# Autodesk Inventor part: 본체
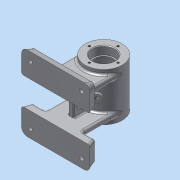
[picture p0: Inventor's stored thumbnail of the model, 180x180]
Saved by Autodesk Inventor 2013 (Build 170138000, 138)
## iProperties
Created: 2016-07
Part Number: 본체
Material: 알루미늄 6061
Document SubType Name: Modeling
Designer: dgall
Density: 1 g/cm^3
Author: dgall
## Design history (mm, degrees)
sketch "스케치1"
  geometry: C1 r 27 at (0, 0); 1 further point
  constraints: 1 centre point, 1 coincident
  dimensions: "d0" = 54 diameter of C1
extrude "돌출1" new body sketch "스케치1" distance "d2" = 70; taper "d3" = 0 deg
node "작업 평면1"
sketch "스케치2"
  geometry: L1 (27, 70)-(-27, 70) reference; L2 (-27, 0)-(27, 0) reference; L3 (50, 90)-(-50, 90); L4 (-50, 90)-(-50, -20); L5 (-50, -20)-(50, -20); L6 (50, -20)-(50, 90); L7 (27, 0)-(27, 70) reference; L8 (-27, 0)-(-27, 70) reference; 5 further points
  constraints: 8 end point, 4 midpoint, 2 parallel, 1 horizontal, 1 horizontal alignment, 1 perpendicular, 1 vertical alignment
  dimensions: "d5" = 100 distance between parallel lines of L4 L6; "d7" = 110 distance between parallel lines of L3 L5
extrude "돌출2" join sketch "스케치2" distance "d8" = 12; taper "d9" = -20 deg
sketch "스케치3"
  geometry: L1 (-70, 55)-(-58, 55); L2 (-58, 55)-(-58, 15); L3 (-58, 15)-(-70, 15); L4 (-70, 15)-(-70, 55); L5 (-58, -15.632)-(-58, 85.632) reference; L6 (-70, 90)-(-70, -20) reference; 6 further points
  constraints: 8 end point, 5 midpoint, 3 coincident, 2 parallel, 1 horizontal, 1 perpendicular
  dimensions: "d10" = 40 distance of L3.end L1.start
extrude "돌출3" cut sketch "스케치3" stored distance "d12" = 12; taper "d13" = 0 deg
sketch "스케치4"
  geometry: L1 (4.368, 12)-(95.632, 12) reference; L2 (23, 70)-(23, 12); L3 (77, 12)-(77, 70); A1 r 27 centre (50, 70) between (23, 70) and (77, 70) reference; 1 further point
  constraints: 4 end point, 2 perpendicular, 2 point on circle, 2 point on line, 1 parallel
  dimensions: "d14" = 54 distance between parallel lines of L3 L2
extrude "돌출4" join sketch "스케치4" distance "d15" = 8; taper "d16" = 0 deg
sketch "스케치5"
  geometry: L1 (4.368, 12)-(95.632, 12) reference; L2 (23, 70)-(23, 12); L3 (77, 12)-(77, 70); A1 r 27 centre (50, 70) between (23, 70) and (77, 70) reference; 1 further point
  constraints: 4 end point, 2 parallel, 2 point on circle, 2 point on line, 1 perpendicular
  dimensions: "d17" = 54 distance between parallel lines of L3 L2
extrude "돌출5" join sketch "스케치5" distance "d18" = 8; taper "d19" = 0 deg
sketch "스케치6"
  geometry: L1 (0, 55)-(-58, 55) reference; L2 (-58, 15)-(0, 15) reference; L3 (-48, 55)-(-22, 55); L4 (-22, 55)-(-22, 15); L5 (-22, 15)-(-48, 15); L6 (-48, 15)-(-48, 55); L7 (-34.5, 43)-(-34.5, 27); L8 (-41.5, 27)-(-41.5, 43); L9 (-70, 15)-(-70, -20) reference; L10 (-27, 0)-(-27, 70) reference; A1 r 3.5 centre (-38, 27) between (-41.5, 27) and (-34.5, 27); A2 r 3.5 centre (-38, 43) between (-34.5, 43) and (-41.5, 43); 3 further points
  constraints: 12 end point, 4 parallel, 4 point on circle, 4 tangent, 2 centre point, 2 midpoint, 2 point on line, 1 horizontal, 1 horizontal alignment, 1 perpendicular
  dimensions: "d20" = 3.5 radius of A1; "d22" = 32 distance from line of L9 A1.centre; "d23" = 23 dimension on A2 A1; "d24" = 21 distance between parallel lines of L6 L10; "d25" = 5 distance between parallel lines of L10 L4
extrude "돌출6" join sketch "스케치6" stored distance "d26" = 8; taper "d27" = 0 deg
node "작업 평면2"
sketch "스케치7"
  geometry: L1 (-27, 0)-(-27, 70) reference; L2 (27, 0)-(27, 70) reference; L3 (27, 70)-(-27, 70) reference; L4 (-27, 0)-(27, 0) reference; C1 r 5 at (0, 22); 2 further points
  constraints: 1 centre point, 1 midpoint, 1 vertical alignment
  dimensions: "d28" = 22 distance of point (0, 0) C1.centre; "d29" = 10 diameter of C1
extrude "돌출7" join sketch "스케치7" distance "d30" = 3; taper "d32" = 0 deg; dims "d31" = 1.5, "d33" = 0
node "작업 평면3"
sketch "스케치9"
  geometry: C1 r 27 at (0, 0) reference; C2 r 16 at (0, 0)
  constraints: 1 centre point, 1 coincident
  dimensions: "d40" = 32 diameter of C2
extrude "돌출8" cut sketch "스케치9" distance "d42" = 12; taper "d43" = 0 deg
sketch "스케치10"
  geometry: C1 r 16 at (0, 0) reference; C2 r 14 at (0, 0)
  constraints: 1 centre point, 1 coincident
  dimensions: "d44" = 28 diameter of C2
extrude "돌출9" cut sketch "스케치10" stored distance "d46" = 12; taper "d47" = 0 deg
sketch "스케치11"
  geometry: C1 r 22 at (0, 0); 1 further point
  constraints: 1 centre point, 1 coincident
  dimensions: "d48" = 44 diameter of C1
extrude "돌출10" cut sketch "스케치11" stored distance "d50" = 42; taper "d51" = 0 deg
chamfer "모따기1" distance "d52" = 1; stored, may be unused: second distance "d53" = 2, angle "d54" = 45 deg
fillet "모깎기1" dims "d55" = 0.3
fillet "모깎기2" dims "d56" = 3
fillet "모깎기3" dims "d57" = 2
fillet "모깎기4" dims "d58" = 10, "d59" = 5
fillet "모깎기5" dims "d60" = 10, "d61" = 5
fillet "모깎기6" dims "d62" = 10, "d63" = 5
fillet "모깎기7" dims "d64" = 10, "d65" = 5
fillet "모깎기8" dims "d66" = 3
hole "구멍1" diameter "d69" = 5.188; stored, may be unused: countersink angle "d73" = 90 deg, drill point angle "d75" = 118 deg; dims "d67" = 10, "d68" = 10, "d70" = 10, "d71" = 4, "d72" = 2, "d74" = 8
sketch "스케치12"
  geometry: L1 (30, -12)-(30, -10) reference; L2 (43.532, -12)-(30, -12) reference; L3 (43.532, 11.433)-(43.532, -12) reference; L4 (-41.433, 13.532)-(41.433, 13.532) reference; L5 (-43.532, -12)-(-43.532, 11.433) reference; L6 (-30, -12)-(-43.532, -12) reference; L7 (-30, -10)-(-30, -12) reference; L8 (24, -4)-(-24, -4) reference; L9 (-41.555, -90)-(41.555, -90) reference; L10 (-50, -55)-(-50, -81.555) reference; A1 r 6 centre (24, -10) between (30, -10) and (24, -4) reference; A2 r 6 centre (-24, -10) between (-24, -4) and (-30, -10) reference; 5 further points
  constraints: 2 horizontal alignment, 2 vertical alignment, 2 other
  dimensions: "d85" = 75 distance of point (37.5, -77.5) point (-37.5, -77.5); "d87" = 85 distance of point (-37.5, -77.5) point (-37.5, 7.5); "d88" = 12.5 distance from line of L9 point (-37.5, -77.5); "d89" = 12.5 distance from line of L10 point (-37.5, -77.5)
hole "구멍3" sketch "스케치12" at (-37.5, -77.5), (-37.5, 7.5), (37.5, 7.5), (37.5, -77.5) diameter "d90" = 6; stored, may be unused: countersink angle "d94" = 90 deg, drill point angle "d96" = 118 deg; dims "d91" = 10, "d92" = 10, "d93" = 4, "d95" = 8
sketch "스케치13"
  geometry: C1 r 27 at (0, 0) reference; 1 further point
  constraints: 1 vertical alignment
  dimensions: "d97" = 21 distance of C1.centre point (0, 21)
hole "구멍4" sketch "스케치13" at (0, 21) diameter "d98" = 3.242; stored, may be unused: countersink angle "d102" = 90 deg, drill point angle "d104" = 118 deg; dims "d99" = 8, "d100" = 10, "d101" = 4, "d103" = 10
fillet "모깎기9" dims "d108" = 2
node "작업 평면4"
sketch "스케치14"
  geometry: L1 (-27, 0)-(-27, 70) reference; 2 further points
  constraints: 1 other
  dimensions: "d109" = 35 distance of point (0, 35) point (0, 0); "d110" = 27 distance from line of point (0, 35) L1
feature "엠보싱1" sketch "스케치14" dims "d0" = 54, "d111" = 0.5, "d112" = 0
node "작업 평면5"
sketch "스케치15"
  geometry: L1 (0, 0)-(-15.898, -25.441); L2 (-15.898, -25.441)-(-10.809, -28.621); L3 (-10.809, -28.621)-(-8.862, -25.504); L4 (-15.898, -25.441)-(-14.308, -22.897); A1 r 27 centre (0, 0) between (-21.6, -16.2) and (-5.586, -26.416) reference; 1 further point
  constraints: 8 end point, 3 point on circle, 1 parallel, 1 perpendicular, 1 point on line, 1 vertical alignment
  dimensions: "d116" = 32 deg dimension on L1.start L1.end point (0, -27); "d117" = 12 diameter of L3 L1; "d130" = 30 distance from line of L2 L1.start
revolve "회전2" sketch "스케치15" stored, may be unused: angle "d120" = 90 deg
hole "구멍5" diameter "d123" = 5.188; stored, may be unused: countersink angle "d127" = 90 deg, drill point angle "d129" = 118 deg; dims "d121" = 10, "d122" = 10, "d124" = 30, "d125" = 4, "d126" = 2, "d128" = 8
node "솔리드1"
mirror "대칭1"
pattern_circular "원형 패턴1" dims angle "d106" = 360 deg
mirror "대칭2"
node "투영된 루프1"
node "투영된 루프2"
node "투영된 루프3"
other parameters: "d34" = -35, "d114" = -35
